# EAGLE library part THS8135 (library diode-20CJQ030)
TI THS8135 TRIPLE 10-BIT, 240 MSPS VIDEO DAC WITH TRI-LEVEL SYNC AND VIDEO (ITU-R.BT601)?COMPLIANT FULL SCALE RANGE Features: Triple 10-Bit D/A Converters 240-MSPS Operation YPbPr/RGB Configurable Blanking Levels, Correctly Positioned for Either Full (0-1023) or Video (ITU-R.BT601) -Compliant Input Code Ranges Generic Triple DAC Mode for Non-Video Applications Direct Drive of Double-Terminated 75-? Load Into Standard Video Levels 3x10 Bit 4:4:4, 2x10 Bit 4:2:2 or 1x10 Bit 4:2:2 (ITU-R.BT656) Multiplexed YCbCr/GBR Input Data Formats Bi-Level (EIA) or Tri-Level (SMPTE) Sync Generation Integrated Sync-On-Green/Luminance or Sync-On-All Composite Sync Insertion Internal Voltage Reference Low-Power Operation From 3.3-V Analog and 1.8-V Digital Suply Levels Applications: High-Definition Television (HDTV) Set-Top Boxes/Receivers/Displays High-Resolution Image Processing Please send any comments to: messi@users.sourceforge.net
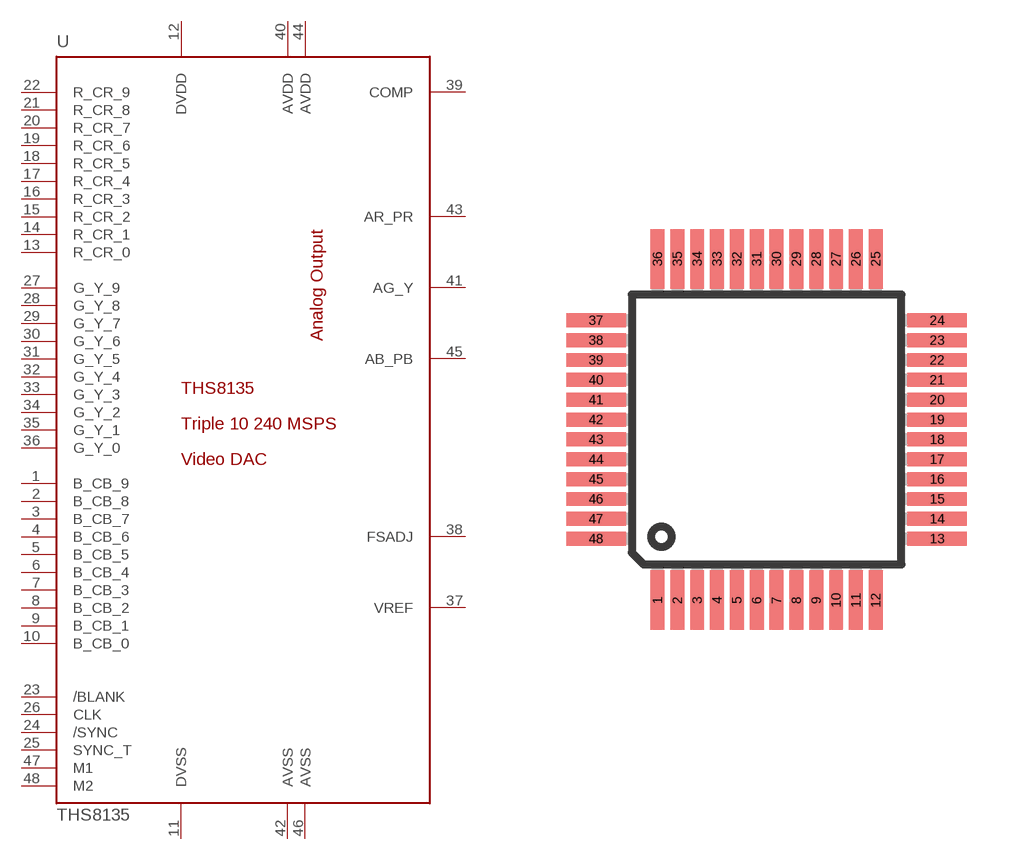
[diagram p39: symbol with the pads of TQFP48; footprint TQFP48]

Designator prefix U

## THS8135  [TQFP48]
1  B_CB_9  in
2  B_CB_8  in
3  B_CB_7  in
4  B_CB_6  in
5  B_CB_5  in
6  B_CB_4  in
7  B_CB_3  in
8  B_CB_2  in
9  B_CB_1  in
10  B_CB_0  in
11  DVSS  pwr
12  DVDD  pwr
13  R_CR_0  in
14  R_CR_1  in
15  R_CR_2  in
16  R_CR_3  in
17  R_CR_4  in
18  R_CR_5  in
19  R_CR_6  in
20  R_CR_7  in
21  R_CR_8  in
22  R_CR_9  in
23  /BLANK  in
24  /SYNC  in
25  SYNC_T  in
26  CLK  in
27  G_Y_9  in
28  G_Y_8  in
29  G_Y_7  in
30  G_Y_6  in
31  G_Y_5  in
32  G_Y_4  in
33  G_Y_3  in
34  G_Y_2  in
35  G_Y_1  in
36  G_Y_0  in
37  VREF  out
38  FSADJ  in
39  COMP  out
40  AVDD  pwr
41  AG_Y  out
42  AVSS  pwr
43  AR_PR  out
44  AVDD  pwr
45  AB_PB  out
46  AVSS  pwr
47  M1  in
48  M2  in

## Footprint TQFP48 (pad centres in mm)
THIN QUAD FLAT PACK
smd 0.35 x 1.5: 1 -2.75,-4.25; 2 -2.25,-4.25; 3 -1.75,-4.25; 4 -1.25,-4.25; 5 -0.75,-4.25; 6 -0.25,-4.25; 7 0.25,-4.25; 8 0.75,-4.25; 9 1.25,-4.25; 10 1.75,-4.25; 11 2.25,-4.25; 12 2.75,-4.25; 25 2.75,4.35; 26 2.25,4.35; 27 1.75,4.35; 28 1.25,4.35; 29 0.75,4.35; 30 0.25,4.35; 31 -0.25,4.35; 32 -0.75,4.35; 33 -1.25,4.35; 34 -1.75,4.35; 35 -2.25,4.35; 36 -2.75,4.35
smd 1.5 x 0.35: 13 4.3,-2.7; 14 4.3,-2.2; 15 4.3,-1.7; 16 4.3,-1.2; 17 4.3,-0.7; 18 4.3,-0.2; 19 4.3,0.3; 20 4.3,0.8; 21 4.3,1.3; 22 4.3,1.8; 23 4.3,2.3; 24 4.3,2.8; 37 -4.3,2.8; 38 -4.3,2.3; 39 -4.3,1.8; 40 -4.3,1.3; 41 -4.3,0.8; 42 -4.3,0.3; 43 -4.3,-0.2; 44 -4.3,-0.7; 45 -4.3,-1.2; 46 -4.3,-1.7; 47 -4.3,-2.2; 48 -4.3,-2.7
